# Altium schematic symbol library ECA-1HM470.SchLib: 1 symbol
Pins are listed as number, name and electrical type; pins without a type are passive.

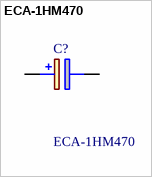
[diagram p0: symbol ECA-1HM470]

## ECA-1HM470
designator C?
Panasonic 47uF +/-20% 50 V dc Through Hole Radial Aluminium Electrolytic Capacitor; Geometry.Height: 12.2mm
footprint CAPPRD250W55D630H1220
pins: 1 +, 2 -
